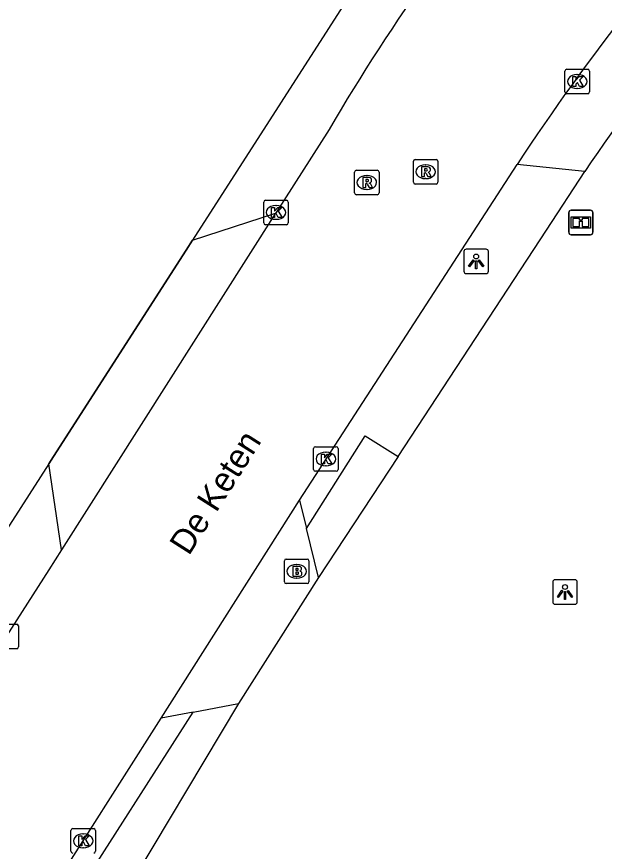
# Model space of a CAD drawing. Extents: x 156141 to 158132, y 385651 to 388399.
# Drawn here: x 156655.7 to 156679.65, y 386680.89 to 386714.89 of the extents above; entities that cross this region are included whole.
import ezdxf

# ---------------------------------------------------------------- set-up
doc = ezdxf.new("R2010")
doc.units = 0
for name, color, linetype in [('IMGEO_Berm_groen', 7, 'Continuous'), ('IMGEO_Brandkraan', 7, 'Continuous'), ('IMGEO_Hek', 7, 'Continuous'), ('IMGEO_Informatiebord', 7, 'Continuous'), ('IMGEO_Kolk', 7, 'Continuous'), ('IMGEO_Lichtpunt', 7, 'Continuous'), ('IMGEO_Openbare_ruimte_label', 7, 'Continuous'), ('IMGEO_Rijbaan_lokaal_gesloten', 7, 'Continuous'), ('IMGEO_Rijbaan_lokaal_open', 7, 'Continuous'), ('IMGEO_Rioolput', 7, 'Continuous'), ('IMGEO_Voetpad_open', 7, 'Continuous')]:
    doc.layers.add(name, color=color, linetype=linetype)

msp = doc.modelspace()

# ---------------------------------------------------------------- linework, layer by layer
at = {"layer": 'IMGEO_Berm_groen'}
for points in [[(156672.017, 386720.053), (156662.858, 386705.786)], [(156671.237, 386696.974), (156677.295, 386706.19), (156678.848, 386708.592)], [(156657.011, 386696.678), (156628.043, 386651.553)]]:
    msp.add_lwpolyline(points, dxfattribs=at)
at = {"layer": 'IMGEO_Brandkraan'}
for p, q in [((156666.606, 386691.871), (156666.606, 386692.723)), ((156666.681, 386692.797), (156667.533, 386692.797)), ((156667.094, 386692.577), (156667.119, 386692.577)), ((156667.607, 386692.723), (156667.607, 386691.871)), ((156667.117, 386692.017), (156667.092, 386692.017)), ((156667.533, 386691.797), (156666.681, 386691.797))]:
    msp.add_line(p, q, dxfattribs=at)
for points in [[(156666.606, 386691.871), (156666.606, 386692.723)], [(156666.681, 386692.797), (156667.533, 386692.797)], [(156666.954, 386692.497), (156666.954, 386692.097), (156667.167, 386692.097)], [(156667.185, 386692.497), (156666.954, 386692.497)], [(156667.607, 386692.723), (156667.607, 386691.871)], [(156667.133, 386692.416), (156667.079, 386692.416), (156667.079, 386692.34)], [(156667.079, 386692.34), (156667.132, 386692.34)], [(156667.141, 386692.264), (156667.079, 386692.264), (156667.079, 386692.183)], [(156667.079, 386692.183), (156667.141, 386692.183)], [(156667.533, 386691.797), (156666.681, 386691.797)]]:
    msp.add_lwpolyline(points, dxfattribs=at)
for centre, radius, start, end in [((156666.683, 386692.721), 0.0765, 91.552, 178.448), ((156666.683, 386692.721), 0.0765, 91.552, 178.448), ((156667.189, 386692.352), 0.145, 59.4692, 91.5367), ((156667.531, 386692.721), 0.0765, 1.552, 88.448), ((156667.531, 386692.721), 0.0765, 1.552, 88.448), ((156667.134, 386692.378), 0.0379, 267.8285, 90.9355), ((156667.142, 386692.223), 0.0404, 269.8759, 90.5077), ((156667.214, 386692.399), 0.0922, 285.5137, 58.1501), ((156667.219, 386692.207), 0.105, 301.3115, 78.989), ((156666.683, 386691.873), 0.0765, 181.552, 268.448), ((156666.683, 386691.873), 0.0765, 181.552, 268.448), ((156667.173, 386692.348), 0.251, 268.6676, 293.5347), ((156667.531, 386691.873), 0.0765, 271.552, 358.448), ((156667.531, 386691.873), 0.0765, 271.552, 358.448)]:
    msp.add_arc(centre, radius, start, end, dxfattribs=at)
for centre, major_axis, ratio, start_param, end_param in [((156667.093, 386692.297), (-0.387, 0.002), 0.722429, 4.712389, 7.853982), ((156667.118, 386692.297), (-0.39, 0.002), 0.717154, 1.570796, 4.712389)]:
    msp.add_ellipse(centre, major_axis=major_axis, ratio=ratio, start_param=start_param, end_param=end_param, dxfattribs=at)
at = {"layer": 'IMGEO_Hek'}
for points in [[(156672.017, 386720.053), (156662.858, 386705.786), (156662.597, 386705.379)], [(156662.597, 386705.379), (156657.201, 386696.974)], [(156657.201, 386696.974), (156657.011, 386696.678), (156628.043, 386651.553)]]:
    msp.add_lwpolyline(points, dxfattribs=at)
at = {"layer": 'IMGEO_Informatiebord'}
for p, q in [((156678.193, 386706.11), (156678.193, 386706.91)), ((156678.193, 386706.91), (156678.193, 386706.11)), ((156678.293, 386707.01), (156679.083, 386707.01)), ((156679.083, 386707.01), (156678.293, 386707.01)), ((156679.183, 386706.91), (156679.183, 386706.11)), ((156679.183, 386706.11), (156679.183, 386706.91)), ((156679.083, 386706.01), (156678.293, 386706.01)), ((156678.293, 386706.01), (156679.083, 386706.01))]:
    msp.add_line(p, q, dxfattribs=at)
for points in [[(156678.294, 386706.742), (156679.082, 386706.742), (156679.082, 386706.278), (156678.294, 386706.278), (156678.294, 386706.742)], [(156678.359, 386706.677), (156678.359, 386706.343), (156678.634, 386706.343), (156678.635, 386706.556), (156678.739, 386706.557), (156678.74, 386706.343), (156679.017, 386706.343), (156679.017, 386706.677), (156678.741, 386706.677), (156678.741, 386706.597), (156678.635, 386706.597), (156678.635, 386706.677), (156678.359, 386706.677)]]:
    msp.add_lwpolyline(points, dxfattribs=at)
for centre, start, end in [((156678.293, 386706.91), 90, 180), ((156678.293, 386706.91), 90, 180), ((156679.083, 386706.91), 0, 90), ((156679.083, 386706.91), 360, 90), ((156678.293, 386706.11), 180, 270), ((156678.293, 386706.11), 180, 270), ((156679.083, 386706.11), 270, 0), ((156679.083, 386706.11), 270, 0)]:
    msp.add_arc(centre, 0.1, start, end, dxfattribs=at)
at = {"layer": 'IMGEO_Kolk'}
for p, q in [((156678.042, 386711.827), (156678.042, 386712.679)), ((156678.117, 386712.753), (156678.969, 386712.753)), ((156679.043, 386712.679), (156679.043, 386711.827)), ((156678.53, 386712.533), (156678.555, 386712.533)), ((156678.553, 386711.973), (156678.528, 386711.973)), ((156678.969, 386711.753), (156678.117, 386711.753)), ((156665.765, 386706.491), (156665.765, 386707.343)), ((156665.84, 386707.417), (156666.692, 386707.417)), ((156666.253, 386707.197), (156666.278, 386707.197)), ((156666.766, 386707.343), (156666.766, 386706.491)), ((156666.276, 386706.637), (156666.251, 386706.637)), ((156666.692, 386706.417), (156665.84, 386706.417)), ((156667.796, 386696.447), (156667.796, 386697.299)), ((156667.871, 386697.373), (156668.723, 386697.373)), ((156668.797, 386697.299), (156668.797, 386696.447)), ((156668.284, 386697.153), (156668.309, 386697.153)), ((156668.307, 386696.593), (156668.282, 386696.593)), ((156668.723, 386696.373), (156667.871, 386696.373)), ((156654.843, 386690.145), (156655.695, 386690.145)), ((156655.769, 386690.071), (156655.769, 386689.219)), ((156655.695, 386689.145), (156654.843, 386689.145)), ((156657.907, 386680.892), (156657.907, 386681.744)), ((156657.982, 386681.818), (156658.834, 386681.818)), ((156658.908, 386681.744), (156658.908, 386680.892)), ((156658.395, 386681.598), (156658.42, 386681.598)), ((156658.418, 386681.038), (156658.393, 386681.038))]:
    msp.add_line(p, q, dxfattribs=at)
for points in [[(156678.042, 386711.827), (156678.042, 386712.679)], [(156678.117, 386712.753), (156678.969, 386712.753)], [(156679.043, 386712.679), (156679.043, 386711.827)], [(156678.363, 386712.453), (156678.486, 386712.453), (156678.486, 386712.302), (156678.616, 386712.453), (156678.78, 386712.453), (156678.634, 386712.302), (156678.787, 386712.053), (156678.635, 386712.053), (156678.55, 386712.217), (156678.486, 386712.15), (156678.486, 386712.053), (156678.363, 386712.053), (156678.363, 386712.453)], [(156678.969, 386711.753), (156678.117, 386711.753)], [(156665.765, 386706.491), (156665.765, 386707.343)], [(156665.84, 386707.417), (156666.692, 386707.417)], [(156666.766, 386707.343), (156666.766, 386706.491)], [(156666.086, 386707.117), (156666.209, 386707.117), (156666.209, 386706.966), (156666.339, 386707.117), (156666.503, 386707.117), (156666.357, 386706.966), (156666.51, 386706.717), (156666.358, 386706.717), (156666.273, 386706.881), (156666.209, 386706.814), (156666.209, 386706.717), (156666.086, 386706.717), (156666.086, 386707.117)], [(156666.692, 386706.417), (156665.84, 386706.417)], [(156667.796, 386696.447), (156667.796, 386697.299)], [(156667.871, 386697.373), (156668.723, 386697.373)], [(156668.797, 386697.299), (156668.797, 386696.447)], [(156668.117, 386697.073), (156668.24, 386697.073), (156668.24, 386696.922), (156668.37, 386697.073), (156668.534, 386697.073), (156668.388, 386696.922), (156668.541, 386696.673), (156668.389, 386696.673), (156668.304, 386696.837), (156668.24, 386696.77), (156668.24, 386696.673), (156668.117, 386696.673), (156668.117, 386697.073)], [(156668.723, 386696.373), (156667.871, 386696.373)], [(156654.843, 386690.145), (156655.695, 386690.145)], [(156655.769, 386690.071), (156655.769, 386689.219)], [(156655.695, 386689.145), (156654.843, 386689.145)], [(156657.907, 386680.892), (156657.907, 386681.744)], [(156657.982, 386681.818), (156658.834, 386681.818)], [(156658.908, 386681.744), (156658.908, 386680.892)], [(156658.228, 386681.518), (156658.351, 386681.518), (156658.351, 386681.367), (156658.481, 386681.518), (156658.645, 386681.518), (156658.499, 386681.367), (156658.652, 386681.118), (156658.5, 386681.118), (156658.415, 386681.282), (156658.351, 386681.215), (156658.351, 386681.118), (156658.228, 386681.118), (156658.228, 386681.518)]]:
    msp.add_lwpolyline(points, dxfattribs=at)
for centre, start, end in [((156678.119, 386712.677), 91.552, 178.448), ((156678.119, 386712.677), 91.552, 178.448), ((156678.967, 386712.677), 1.552, 88.448), ((156678.967, 386712.677), 1.552, 88.448), ((156678.119, 386711.829), 181.552, 268.448), ((156678.119, 386711.829), 181.552, 268.448), ((156678.967, 386711.829), 271.552, 358.448), ((156678.967, 386711.829), 271.552, 358.448), ((156665.842, 386707.341), 91.552, 178.448), ((156665.842, 386707.341), 91.552, 178.448), ((156666.69, 386707.341), 1.552, 88.448), ((156666.69, 386707.341), 1.552, 88.448), ((156665.842, 386706.493), 181.552, 268.448), ((156665.842, 386706.493), 181.552, 268.448), ((156666.69, 386706.493), 271.552, 358.448), ((156666.69, 386706.493), 271.552, 358.448), ((156667.873, 386697.297), 91.552, 178.448), ((156667.873, 386697.297), 91.552, 178.448), ((156668.721, 386697.297), 1.552, 88.448), ((156668.721, 386697.297), 1.552, 88.448), ((156667.873, 386696.449), 181.552, 268.448), ((156667.873, 386696.449), 181.552, 268.448), ((156668.721, 386696.449), 271.552, 358.448), ((156668.721, 386696.449), 271.552, 358.448), ((156655.693, 386690.069), 1.552, 88.448), ((156655.693, 386690.069), 1.552, 88.448), ((156655.693, 386689.221), 271.552, 358.448), ((156655.693, 386689.221), 271.552, 358.448), ((156657.984, 386681.742), 91.552, 178.448), ((156657.984, 386681.742), 91.552, 178.448), ((156658.832, 386681.742), 1.552, 88.448), ((156658.832, 386681.742), 1.552, 88.448), ((156657.984, 386680.894), 181.552, 268.448), ((156657.984, 386680.894), 181.552, 268.448), ((156658.832, 386680.894), 271.552, 358.448), ((156658.832, 386680.894), 271.552, 358.448)]:
    msp.add_arc(centre, 0.0765, start, end, dxfattribs=at)
for centre, major_axis, ratio, start_param, end_param in [((156678.529, 386712.253), (-0.387, 0.002), 0.722429, 4.712389, 7.853982), ((156678.554, 386712.253), (-0.39, 0.002), 0.717154, 1.570796, 4.712389), ((156666.252, 386706.917), (-0.387, 0.002), 0.722429, 4.712389, 7.853982), ((156666.277, 386706.917), (-0.39, 0.002), 0.717154, 1.570796, 4.712389), ((156668.283, 386696.873), (-0.387, 0.002), 0.722429, 4.712389, 7.853982), ((156668.308, 386696.873), (-0.39, 0.002), 0.717154, 1.570796, 4.712389), ((156658.394, 386681.318), (-0.387, 0.002), 0.722429, 4.712389, 7.853982), ((156658.419, 386681.318), (-0.39, 0.002), 0.717154, 1.570796, 4.712389)]:
    msp.add_ellipse(centre, major_axis=major_axis, ratio=ratio, start_param=start_param, end_param=end_param, dxfattribs=at)
at = {"layer": 'IMGEO_Lichtpunt'}
for p, q in [((156674.827, 386705.421), (156674.019, 386705.421)), ((156674.827, 386705.421), (156674.019, 386705.421)), ((156673.925, 386705.326), (156673.925, 386704.519)), ((156673.925, 386705.326), (156673.925, 386704.519)), ((156674.921, 386704.519), (156674.921, 386705.326)), ((156674.921, 386704.519), (156674.921, 386705.326)), ((156674.019, 386704.425), (156674.827, 386704.425)), ((156674.019, 386704.425), (156674.827, 386704.425)), ((156677.544, 386691.86), (156677.544, 386691.053)), ((156677.544, 386691.86), (156677.544, 386691.053)), ((156678.446, 386691.955), (156677.638, 386691.955)), ((156678.446, 386691.955), (156677.638, 386691.955)), ((156678.54, 386691.053), (156678.54, 386691.86)), ((156678.54, 386691.053), (156678.54, 386691.86)), ((156677.638, 386690.959), (156678.446, 386690.959)), ((156677.638, 386690.959), (156678.446, 386690.959))]:
    msp.add_line(p, q, dxfattribs=at)
for points in [[(156674.299, 386704.99), (156674.338, 386704.962), (156674.15, 386704.7), (156674.112, 386704.727), (156674.299, 386704.99)], [(156674.401, 386704.942), (156674.448, 386704.942), (156674.448, 386704.62), (156674.401, 386704.62), (156674.401, 386704.942)], [(156674.511, 386704.962), (156674.549, 386704.989), (156674.736, 386704.727), (156674.697, 386704.699), (156674.511, 386704.962)], [(156677.918, 386691.524), (156677.957, 386691.496), (156677.769, 386691.234), (156677.731, 386691.261), (156677.918, 386691.524)], [(156678.13, 386691.496), (156678.168, 386691.523), (156678.355, 386691.261), (156678.316, 386691.233), (156678.13, 386691.496)], [(156678.02, 386691.476), (156678.067, 386691.476), (156678.067, 386691.154), (156678.02, 386691.154), (156678.02, 386691.476)]]:
    msp.add_lwpolyline(points, dxfattribs=at)
for centre in [(156674.424, 386705.124), (156678.043, 386691.658)]:
    msp.add_circle(centre, 0.0994, dxfattribs=at)
for centre, start, end in [((156674.019, 386705.326), 90, 180), ((156674.019, 386705.326), 90, 180), ((156674.827, 386705.326), 0, 90), ((156674.827, 386705.326), 0, 90), ((156674.019, 386704.519), 180, 270), ((156674.019, 386704.519), 180, 270), ((156674.827, 386704.519), 270, 0), ((156674.827, 386704.519), 270, 360), ((156677.638, 386691.86), 90, 180), ((156677.638, 386691.86), 90, 180), ((156678.446, 386691.86), 0, 90), ((156678.446, 386691.86), 0, 90), ((156677.638, 386691.053), 180, 270), ((156677.638, 386691.053), 180, 270), ((156678.446, 386691.053), 270, 0), ((156678.446, 386691.053), 270, 360)]:
    msp.add_arc(centre, 0.0946, start, end, dxfattribs=at)
at = {"layer": 'IMGEO_Rijbaan_lokaal_gesloten'}
for points in [[(156668.43, 386710.299), (156666.266, 386706.917), (156666.247, 386706.887)], [(156667.221, 386695.196), (156676.089, 386708.874)], [(156666.247, 386706.887), (156657.521, 386693.171)], [(156661.583, 386686.315), (156667.221, 386695.196)], [(156657.521, 386693.171), (156657.007, 386692.363), (156655.269, 386689.645), (156654.094, 386687.764), (156631.606, 386652.383)], [(156657.828, 386680.422), (156658.407, 386681.319), (156661.583, 386686.315)]]:
    msp.add_lwpolyline(points, dxfattribs=at)
for centre, radius, start, end in [((156760.249, 386653.266), 100.872, 128.41351, 146.54566), ((156738.474, 386669.465), 81.077, 138.86025, 149.75904)]:
    msp.add_arc(centre, radius, start, end, dxfattribs=at)
at = {"layer": 'IMGEO_Rijbaan_lokaal_open'}
for points in [[(156678.848, 386708.592), (156676.089, 386708.874)], [(156662.858, 386705.786), (156666.247, 386706.887)], [(156657.011, 386696.678), (156657.201, 386696.974), (156662.597, 386705.379), (156662.858, 386705.786)], [(156657.521, 386693.171), (156657.011, 386696.678)]]:
    msp.add_lwpolyline(points, dxfattribs=at)
msp.add_arc((156761.599, 386651.828), 100.349, 128.56671, 145.55143, dxfattribs=at)
at = {"layer": 'IMGEO_Rioolput'}
for p, q in [((156671.862, 386708.15), (156671.862, 386709.002)), ((156671.937, 386709.076), (156672.789, 386709.076)), ((156672.35, 386708.856), (156672.375, 386708.856)), ((156672.863, 386709.002), (156672.863, 386708.15)), ((156669.465, 386707.712), (156669.465, 386708.564)), ((156669.54, 386708.638), (156670.392, 386708.638)), ((156670.466, 386708.564), (156670.466, 386707.712)), ((156669.953, 386708.418), (156669.978, 386708.418)), ((156672.373, 386708.296), (156672.348, 386708.296)), ((156669.976, 386707.858), (156669.951, 386707.858)), ((156672.789, 386708.076), (156671.937, 386708.076)), ((156670.392, 386707.638), (156669.54, 386707.638))]:
    msp.add_line(p, q, dxfattribs=at)
for points in [[(156671.862, 386708.15), (156671.862, 386709.002)], [(156671.937, 386709.076), (156672.789, 386709.076)], [(156672.863, 386709.002), (156672.863, 386708.15)], [(156669.465, 386707.712), (156669.465, 386708.564)], [(156669.54, 386708.638), (156670.392, 386708.638)], [(156670.466, 386708.564), (156670.466, 386707.712)], [(156672.451, 386708.774), (156672.199, 386708.776), (156672.199, 386708.376)], [(156672.199, 386708.376), (156672.323, 386708.376), (156672.323, 386708.538), (156672.334, 386708.538)], [(156672.377, 386708.695), (156672.323, 386708.695), (156672.323, 386708.614)], [(156672.323, 386708.614), (156672.375, 386708.614)], [(156672.381, 386708.509), (156672.452, 386708.376), (156672.592, 386708.376), (156672.527, 386708.502)], [(156670.054, 386708.336), (156669.802, 386708.338), (156669.802, 386707.938)], [(156669.98, 386708.257), (156669.926, 386708.257), (156669.926, 386708.176)], [(156669.926, 386708.176), (156669.978, 386708.176)], [(156669.802, 386707.938), (156669.926, 386707.938), (156669.926, 386708.1), (156669.937, 386708.1)], [(156669.984, 386708.071), (156670.055, 386707.938), (156670.195, 386707.938), (156670.13, 386708.064)], [(156672.789, 386708.076), (156671.937, 386708.076)], [(156670.392, 386707.638), (156669.54, 386707.638)]]:
    msp.add_lwpolyline(points, dxfattribs=at)
for centre, radius, start, end in [((156671.939, 386709), 0.0765, 91.552, 178.448), ((156671.939, 386709), 0.0765, 91.552, 178.448), ((156672.787, 386709), 0.0765, 1.552, 88.448), ((156672.787, 386709), 0.0765, 1.552, 88.448), ((156669.542, 386708.562), 0.0765, 91.552, 178.448), ((156669.542, 386708.562), 0.0765, 91.552, 178.448), ((156670.39, 386708.562), 0.0765, 1.552, 88.448), ((156670.39, 386708.562), 0.0765, 1.552, 88.448), ((156672.333, 386708.485), 0.0533, 26.0293, 88.6989), ((156672.359, 386708.803), 0.19, 274.7715, 282.9687), ((156672.383, 386708.599), 0.0964, 77.0061, 93.1865), ((156672.397, 386708.656), 0.0378, 276.6634, 79.6772), ((156672.45, 386708.664), 0.109, 350.3612, 89.416), ((156672.448, 386708.664), 0.112, 277.5842, 350.9817), ((156672.432, 386708.449), 0.108, 29.5134, 73.7905), ((156669.962, 386708.365), 0.19, 274.7715, 282.9687), ((156669.986, 386708.161), 0.0964, 77.0061, 93.1865), ((156670, 386708.218), 0.0378, 276.6634, 79.6772), ((156670.053, 386708.226), 0.109, 350.3612, 89.416), ((156670.051, 386708.226), 0.112, 277.5842, 350.9817), ((156671.939, 386708.152), 0.0765, 181.552, 268.448), ((156671.939, 386708.152), 0.0765, 181.552, 268.448), ((156672.787, 386708.152), 0.0765, 271.552, 358.448), ((156672.787, 386708.152), 0.0765, 271.552, 358.448), ((156669.936, 386708.047), 0.0533, 26.0293, 88.6989), ((156670.035, 386708.011), 0.108, 29.5134, 73.7905), ((156669.542, 386707.714), 0.0765, 181.552, 268.448), ((156669.542, 386707.714), 0.0765, 181.552, 268.448), ((156670.39, 386707.714), 0.0765, 271.552, 358.448), ((156670.39, 386707.714), 0.0765, 271.552, 358.448)]:
    msp.add_arc(centre, radius, start, end, dxfattribs=at)
for centre, major_axis, ratio, start_param, end_param in [((156672.349, 386708.576), (-0.387, 0.002), 0.722429, 4.712389, 7.853982), ((156672.374, 386708.576), (-0.39, 0.002), 0.717154, 1.570796, 4.712389), ((156669.952, 386708.138), (-0.387, 0.002), 0.722429, 4.712389, 7.853982), ((156669.977, 386708.138), (-0.39, 0.002), 0.717154, 1.570796, 4.712389)]:
    msp.add_ellipse(centre, major_axis=major_axis, ratio=ratio, start_param=start_param, end_param=end_param, dxfattribs=at)
at = {"layer": 'IMGEO_Voetpad_open'}
for points in [[(156667.505, 386694.039), (156669.905, 386697.823), (156671.237, 386696.974)], [(156671.237, 386696.974), (156667.996, 386692.043)], [(156667.221, 386695.196), (156667.505, 386694.039)], [(156667.996, 386692.043), (156667.505, 386694.039)], [(156667.996, 386692.043), (156664.741, 386686.914)], [(156664.741, 386686.914), (156659.827, 386678.705), (156658.066, 386675.763)], [(156662.888, 386686.562), (156664.741, 386686.914)], [(156657.907, 386678.767), (156662.888, 386686.562)], [(156662.888, 386686.562), (156661.583, 386686.315)]]:
    msp.add_lwpolyline(points, dxfattribs=at)

# ---------------------------------------------------------------- texts
at = {"layer": 'IMGEO_Openbare_ruimte_label'}
msp.add_text('De Keten', height=1, rotation=57.5816, dxfattribs=at).set_placement((156662.712, 386692.902))

doc.saveas('drawing.dxf')
